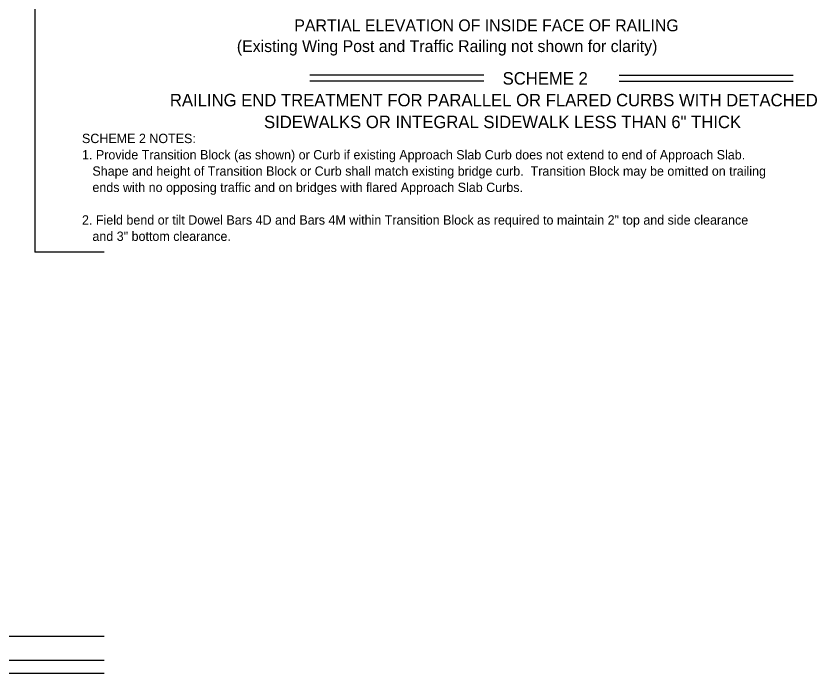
# Model space of a CAD drawing. Extents: x 21526.6 to 21595.9, y 56117 to 56157.3.
# Drawn here: x 21545.31 to 21562.59, y 56118.23 to 56132.42 of the extents above; entities that cross this region are included whole.
import ezdxf

# ---------------------------------------------------------------- set-up
doc = ezdxf.new("R2010")
doc.units = 0
doc.layers.add('Border', color=7, linetype='Continuous')
doc.layers.add('PlotBorder_dp', color=7, linetype='Continuous')

msp = doc.modelspace()

# ---------------------------------------------------------------- linework, layer by layer
at = {"layer": 'Border'}
for p, q in [((21547.212, 56119.023), (21526.6, 56119.023)), ((21547.212, 56118.507), (21526.6, 56118.507)), ((21526.6, 56118.234), (21547.212, 56118.234))]:
    msp.add_line(p, q, dxfattribs=at)
at = {"layer": 'PlotBorder_dp'}
for p, q in [((21545.716, 56153.256), (21545.716, 56127.317)), ((21555.406, 56131.142), (21551.647, 56131.142)), ((21558.321, 56131.142), (21562.08, 56131.142)), ((21555.406, 56131.009), (21551.647, 56131.009)), ((21558.321, 56131.009), (21562.08, 56131.009)), ((21547.212, 56127.317), (21545.716, 56127.317))]:
    msp.add_line(p, q, dxfattribs=at)

# ---------------------------------------------------------------- texts
for s, height, p in [('PARTIAL ELEVATION OF INSIDE FACE OF RAILING', 0.256, (21551.315, 56132.089)), ('(Existing Wing Post and Traffic Railing not shown for clarity)', 0.256, (21550.074, 56131.641)), ('SCHEME 2', 0.2688, (21555.81, 56130.939)), ('RAILING END TREATMENT FOR PARALLEL OR FLARED CURBS WITH DETACHED', 0.2688, (21548.63, 56130.469)), ('SIDEWALKS OR INTEGRAL SIDEWALK LESS THAN 6" THICK', 0.2688, (21550.661, 56129.998)), ('SCHEME 2 NOTES:', 0.2016, (21546.733, 56129.675)), ('1. Provide Transition Block (as shown) or Curb if existing Approach Slab Curb does not extend to end of Approach Slab.  ', 0.2016, (21546.733, 56129.323)), ('   Shape and height of Transition Block or Curb shall match existing bridge curb.  Transition Block may be omitted on trailing ', 0.2016, (21546.733, 56128.971)), ('   ends with no opposing traffic and on bridges with flared Approach Slab Curbs.', 0.2016, (21546.733, 56128.619)), ('2. Field bend or tilt Dowel Bars 4D and Bars 4M within Transition Block as required to maintain 2" top and side clearance ', 0.2016, (21546.733, 56127.915)), ('   and 3" bottom clearance.', 0.2016, (21546.733, 56127.563))]:
    msp.add_text(s, height=height, dxfattribs=at).set_placement(p)

doc.saveas('drawing.dxf')
